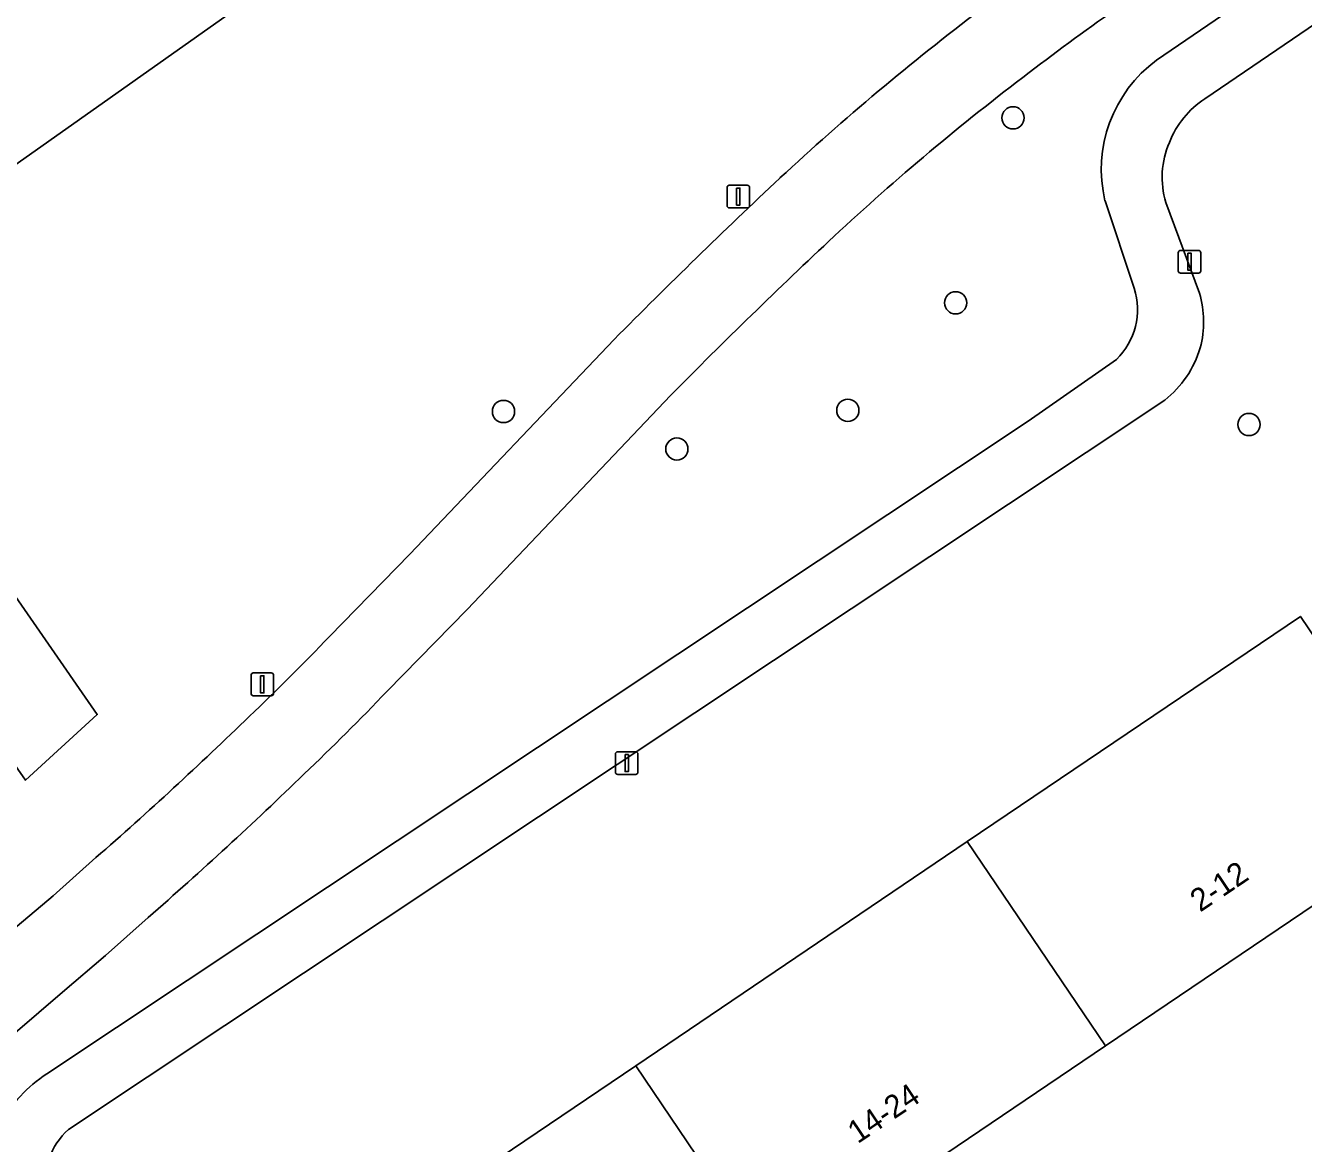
# Model space of a CAD drawing. Extents: x 157445 to 158888, y 383061 to 384688.
# Drawn here: x 157898.8 to 157955, y 383694 to 383743.2 of the extents above; entities that cross this region are included whole.
import ezdxf

# ---------------------------------------------------------------- set-up
doc = ezdxf.new("R2010")
doc.units = 0
for name, color, linetype in [('IMGEO_Boom', 7, 'Continuous'), ('IMGEO_Erf', 7, 'Continuous'), ('IMGEO_Fietspad_gesloten', 7, 'Continuous'), ('IMGEO_Groenvoorziening', 7, 'Continuous'), ('IMGEO_Lichtmast', 7, 'Continuous'), ('IMGEO_Pand', 7, 'Continuous'), ('IMGEO_Pand_nummerreeks', 7, 'Continuous'), ('IMGEO_Voetpad_halfverhard', 7, 'Continuous')]:
    doc.layers.add(name, color=color, linetype=linetype)

msp = doc.modelspace()

# ---------------------------------------------------------------- linework, layer by layer
at = {"layer": 'IMGEO_Boom'}
for centre in [(157942.265, 383739.143), (157939.735, 383731.004), (157919.829, 383726.219), (157934.989, 383726.267), (157952.649, 383725.647), (157927.462, 383724.569)]:
    msp.add_circle(centre, 0.489, dxfattribs=at)
at = {"layer": 'IMGEO_Erf'}
for points in [[(157997.722, 383771.987), (157965.419, 383750), (157950.71, 383739.988)], [(157948.988, 383735.42), (157950.47, 383731.43)], [(157948.946, 383726.721), (157900.671, 383694.616)]]:
    msp.add_lwpolyline(points, dxfattribs=at)
msp.add_lwpolyline([(157946.328, 383698.296), (157931.734, 383688.433), (157917.07, 383678.521), (157910.992, 383687.513), (157925.656, 383697.425), (157940.25, 383707.289), (157954.914, 383717.201), (157960.992, 383708.208)], close=True, dxfattribs=at)
for centre, radius, start, end in [((157953.015, 383736.52), 4.164, 123.616, 158.3149), ((157952.704, 383736.522), 3.876, 156.6316, 196.5159), ((157946.152, 383730.165), 4.5, 345.2429, 16.3254), ((157946.052, 383730.358), 4.648, 308.5078, 343.2533), ((157902.75, 383692.314), 3.101, 132.0913, 189.1552)]:
    msp.add_arc(centre, radius, start, end, dxfattribs=at)
at = {"layer": 'IMGEO_Fietspad_gesloten'}
for points in [[(157924.703, 383729.393), (157915.702, 383719.94), (157912.167, 383716.32)], [(157914.7, 383713.904), (157918.222, 383717.51), (157927.191, 383726.931)], [(157901.88, 383706.584), (157900.005, 383704.908), (157898.141, 383703.326), (157896.062, 383701.531), (157894.337, 383700.082), (157892.352, 383698.448), (157885.736, 383692.998), (157875.014, 383684.462), (157865.358, 383676.882), (157852.047, 383666.43), (157842.421, 383658.73), (157841.961, 383658.361), (157837.589, 383654.846)], [(157836.528, 383648.389), (157837.624, 383649.379), (157842.737, 383653.797), (157844.18, 383655.008), (157844.618, 383655.376), (157853.167, 383662.55), (157853.493, 383662.824), (157867.519, 383674.129), (157877.185, 383681.716), (157887.939, 383690.278), (157894.577, 383695.746), (157896.575, 383697.391), (157898.331, 383698.866), (157900.417, 383700.667), (157902.304, 383702.269), (157904.181, 383703.947)]]:
    msp.add_lwpolyline(points, dxfattribs=at)
for centre, radius, start, end in [((158002.002, 383664.494), 96.738, 121.68559, 127.60385), ((158010.504, 383651.883), 115.421, 127.1273, 132.85408), ((158010.117, 383652.35), 111.316, 127.09842, 132.87131), ((158117.831, 383538.265), 271.713, 133.15038, 135.29828), ((158116.11, 383540.025), 265.753, 133.14295, 135.30686), ((157841.014, 383784.173), 98.32, 313.46082, 316.36001), ((157840.918, 383784.281), 101.964, 313.45835, 316.35287), ((157787.811, 383837.338), 173.518, 311.10144, 314.13695), ((157787.85, 383837.295), 176.959, 311.10099, 314.12423)]:
    msp.add_arc(centre, radius, start, end, dxfattribs=at)
at = {"layer": 'IMGEO_Groenvoorziening'}
for points in [[(157839.994, 383696.696), (157885.522, 383728.992), (157898.786, 383709.993), (157901.945, 383712.881), (157889.492, 383730.847), (157916.616, 383750), (157931.021, 383760.172), (157936.919, 383770.631), (157935.241, 383772.994), (157884.438, 383737.785), (157867.234, 383761.672), (157846.427, 383747.463), (157844.867, 383746.398), (157827.343, 383734.432)], [(157949.351, 383749.791), (157950.978, 383750.786), (157941.242, 383764.543), (157936.919, 383770.631), (157931.021, 383760.172), (157916.616, 383750), (157889.492, 383730.847), (157901.945, 383712.881), (157898.786, 383709.993), (157885.522, 383728.992)], [(157948.585, 383741.682), (157954.431, 383745.691), (157954.668, 383745.864), (157953.117, 383747.991), (157951.19, 383746.813)], [(157947.601, 383731.641), (157946.312, 383735.496)], [(157885.522, 383728.992), (157839.994, 383696.696), (157835.48, 383702.88), (157823.566, 383689.434), (157823.053, 383687.894), (157822.409, 383687.192), (157821.549, 383686.723), (157837.589, 383654.846), (157841.961, 383658.361), (157842.421, 383658.73), (157852.047, 383666.43), (157865.358, 383676.882), (157875.014, 383684.462), (157885.736, 383692.998), (157892.352, 383698.448), (157894.337, 383700.082), (157896.062, 383701.531), (157898.141, 383703.326), (157900.005, 383704.908), (157901.88, 383706.584)], [(157912.167, 383716.32), (157915.702, 383719.94), (157924.703, 383729.393)], [(157942.929, 383725.795), (157946.819, 383728.506)], [(157927.191, 383726.931), (157918.222, 383717.51), (157914.7, 383713.904)], [(157899.722, 383697.07), (157942.929, 383725.795)], [(157904.181, 383703.947), (157902.304, 383702.269), (157900.417, 383700.667), (157898.331, 383698.866), (157896.575, 383697.391), (157894.577, 383695.746), (157887.939, 383690.278), (157877.185, 383681.716), (157867.519, 383674.129), (157853.493, 383662.824), (157853.167, 383662.55), (157844.618, 383655.376), (157844.18, 383655.008), (157842.737, 383653.797), (157842.617, 383653.598)]]:
    msp.add_lwpolyline(points, dxfattribs=at)
for centre, radius, start, end in [((158002.002, 383664.494), 96.738, 121.68559, 127.60385), ((158010.504, 383651.883), 115.421, 127.1273, 132.85408), ((157952.113, 383736.875), 5.963, 126.2764, 193.3726), ((158010.117, 383652.35), 111.316, 127.09842, 132.87131), ((158117.831, 383538.265), 271.713, 133.15038, 135.29828), ((158116.11, 383540.025), 265.753, 133.14295, 135.30686), ((157944.637, 383730.715), 3.105, 314.6389, 17.3489), ((157841.014, 383784.173), 98.32, 313.46082, 316.36001), ((157840.918, 383784.281), 101.964, 313.45835, 316.35287), ((157787.811, 383837.338), 173.518, 311.10144, 314.13695), ((157787.85, 383837.295), 176.959, 311.10099, 314.12423), ((157903.336, 383691.592), 6.563, 123.4117, 150.0223)]:
    msp.add_arc(centre, radius, start, end, dxfattribs=at)
at = {"layer": 'IMGEO_Lichtmast'}
for p, q in [((157929.671, 383735.277), (157929.671, 383736.077)), ((157929.671, 383736.077), (157929.671, 383735.277)), ((157929.771, 383736.177), (157930.561, 383736.177)), ((157930.561, 383736.177), (157929.771, 383736.177)), ((157930.661, 383736.077), (157930.661, 383735.277)), ((157930.661, 383735.277), (157930.661, 383736.077)), ((157930.561, 383735.177), (157929.771, 383735.177)), ((157929.771, 383735.177), (157930.561, 383735.177)), ((157949.54, 383732.409), (157949.54, 383733.209)), ((157949.54, 383733.209), (157949.54, 383732.409)), ((157949.64, 383733.309), (157950.43, 383733.309)), ((157950.43, 383733.309), (157949.64, 383733.309)), ((157950.53, 383733.209), (157950.53, 383732.409)), ((157950.53, 383732.409), (157950.53, 383733.209)), ((157950.43, 383732.309), (157949.64, 383732.309)), ((157949.64, 383732.309), (157950.43, 383732.309)), ((157908.713, 383713.811), (157908.713, 383714.611)), ((157908.713, 383714.611), (157908.713, 383713.811)), ((157908.813, 383714.711), (157909.603, 383714.711)), ((157909.603, 383714.711), (157908.813, 383714.711)), ((157909.703, 383714.611), (157909.703, 383713.811)), ((157909.703, 383713.811), (157909.703, 383714.611)), ((157909.603, 383713.711), (157908.813, 383713.711)), ((157908.813, 383713.711), (157909.603, 383713.711)), ((157924.758, 383710.344), (157924.758, 383711.144)), ((157924.758, 383711.144), (157924.758, 383710.344)), ((157924.858, 383711.244), (157925.648, 383711.244)), ((157925.648, 383711.244), (157924.858, 383711.244)), ((157925.748, 383711.144), (157925.748, 383710.344)), ((157925.748, 383710.344), (157925.748, 383711.144)), ((157925.648, 383710.244), (157924.858, 383710.244)), ((157924.858, 383710.244), (157925.648, 383710.244))]:
    msp.add_line(p, q, dxfattribs=at)
for points in [[(157930.091, 383736.052), (157930.241, 383736.052), (157930.241, 383735.302), (157930.091, 383735.302), (157930.091, 383736.052)], [(157949.96, 383733.184), (157950.11, 383733.184), (157950.11, 383732.434), (157949.96, 383732.434), (157949.96, 383733.184)], [(157909.133, 383714.586), (157909.283, 383714.586), (157909.283, 383713.836), (157909.133, 383713.836), (157909.133, 383714.586)], [(157925.178, 383711.119), (157925.328, 383711.119), (157925.328, 383710.369), (157925.178, 383710.369), (157925.178, 383711.119)]]:
    msp.add_lwpolyline(points, dxfattribs=at)
for centre, start, end in [((157929.771, 383736.077), 90, 180), ((157929.771, 383736.077), 90, 180), ((157930.561, 383736.077), 0, 90), ((157930.561, 383736.077), 360, 90), ((157929.771, 383735.277), 180, 270), ((157929.771, 383735.277), 180, 270), ((157930.561, 383735.277), 270, 0), ((157930.561, 383735.277), 270, 0), ((157949.64, 383733.209), 90, 180), ((157949.64, 383733.209), 90, 180), ((157950.43, 383733.209), 0, 90), ((157950.43, 383733.209), 360, 90), ((157949.64, 383732.409), 180, 270), ((157949.64, 383732.409), 180, 270), ((157950.43, 383732.409), 270, 0), ((157950.43, 383732.409), 270, 0), ((157908.813, 383714.611), 90, 180), ((157908.813, 383714.611), 90, 180), ((157909.603, 383714.611), 0, 90), ((157909.603, 383714.611), 360, 90), ((157908.813, 383713.811), 180, 270), ((157908.813, 383713.811), 180, 270), ((157909.603, 383713.811), 270, 0), ((157909.603, 383713.811), 270, 0), ((157924.858, 383711.144), 90, 180), ((157924.858, 383711.144), 90, 180), ((157925.648, 383711.144), 0, 90), ((157925.648, 383711.144), 360, 90), ((157924.858, 383710.344), 180, 270), ((157924.858, 383710.344), 180, 270), ((157925.648, 383710.344), 270, 0), ((157925.648, 383710.344), 270, 0)]:
    msp.add_arc(centre, 0.1, start, end, dxfattribs=at)
at = {"layer": 'IMGEO_Pand'}
for points in [[(157946.328, 383698.296), (157960.992, 383708.208), (157954.914, 383717.201), (157940.25, 383707.289)], [(157931.734, 383688.433), (157946.328, 383698.296), (157940.25, 383707.289), (157925.656, 383697.425)], [(157931.734, 383688.433), (157925.656, 383697.425), (157910.992, 383687.513), (157917.07, 383678.521)]]:
    msp.add_lwpolyline(points, close=True, dxfattribs=at)
at = {"layer": 'IMGEO_Voetpad_halfverhard'}
for points in [[(157950.71, 383739.988), (157965.419, 383750), (157997.722, 383771.987)], [(157985.877, 383766.914), (157985.746, 383766.817), (157984.197, 383765.698), (157967.336, 383754.363), (157956.607, 383747.15), (157955.101, 383749.204), (157953.117, 383747.991), (157954.668, 383745.864), (157954.431, 383745.691), (157948.585, 383741.682)], [(157946.312, 383735.496), (157947.601, 383731.641)], [(157950.47, 383731.43), (157948.988, 383735.42)], [(157946.819, 383728.506), (157942.929, 383725.795), (157899.722, 383697.07)], [(157900.671, 383694.616), (157948.946, 383726.721)]]:
    msp.add_lwpolyline(points, dxfattribs=at)
for centre, radius, start, end in [((157952.113, 383736.875), 5.963, 126.2764, 193.3726), ((157953.015, 383736.52), 4.164, 123.616, 158.3149), ((157952.704, 383736.522), 3.876, 156.6316, 196.5159), ((157944.637, 383730.715), 3.105, 314.6389, 17.3489), ((157946.152, 383730.165), 4.5, 345.2429, 16.3254), ((157946.052, 383730.358), 4.648, 308.5078, 343.2533), ((157903.336, 383691.592), 6.563, 123.4117, 150.0223), ((157902.75, 383692.314), 3.101, 132.0913, 189.1552)]:
    msp.add_arc(centre, radius, start, end, dxfattribs=at)

# ---------------------------------------------------------------- texts
at = {"layer": 'IMGEO_Pand_nummerreeks'}
for s, p in [('2-12', (157950.501, 383704.159)), ('14-24', (157935.421, 383693.966))]:
    msp.add_text(s, height=1, rotation=34.0549, dxfattribs=at).set_placement(p)

doc.saveas('drawing.dxf')
